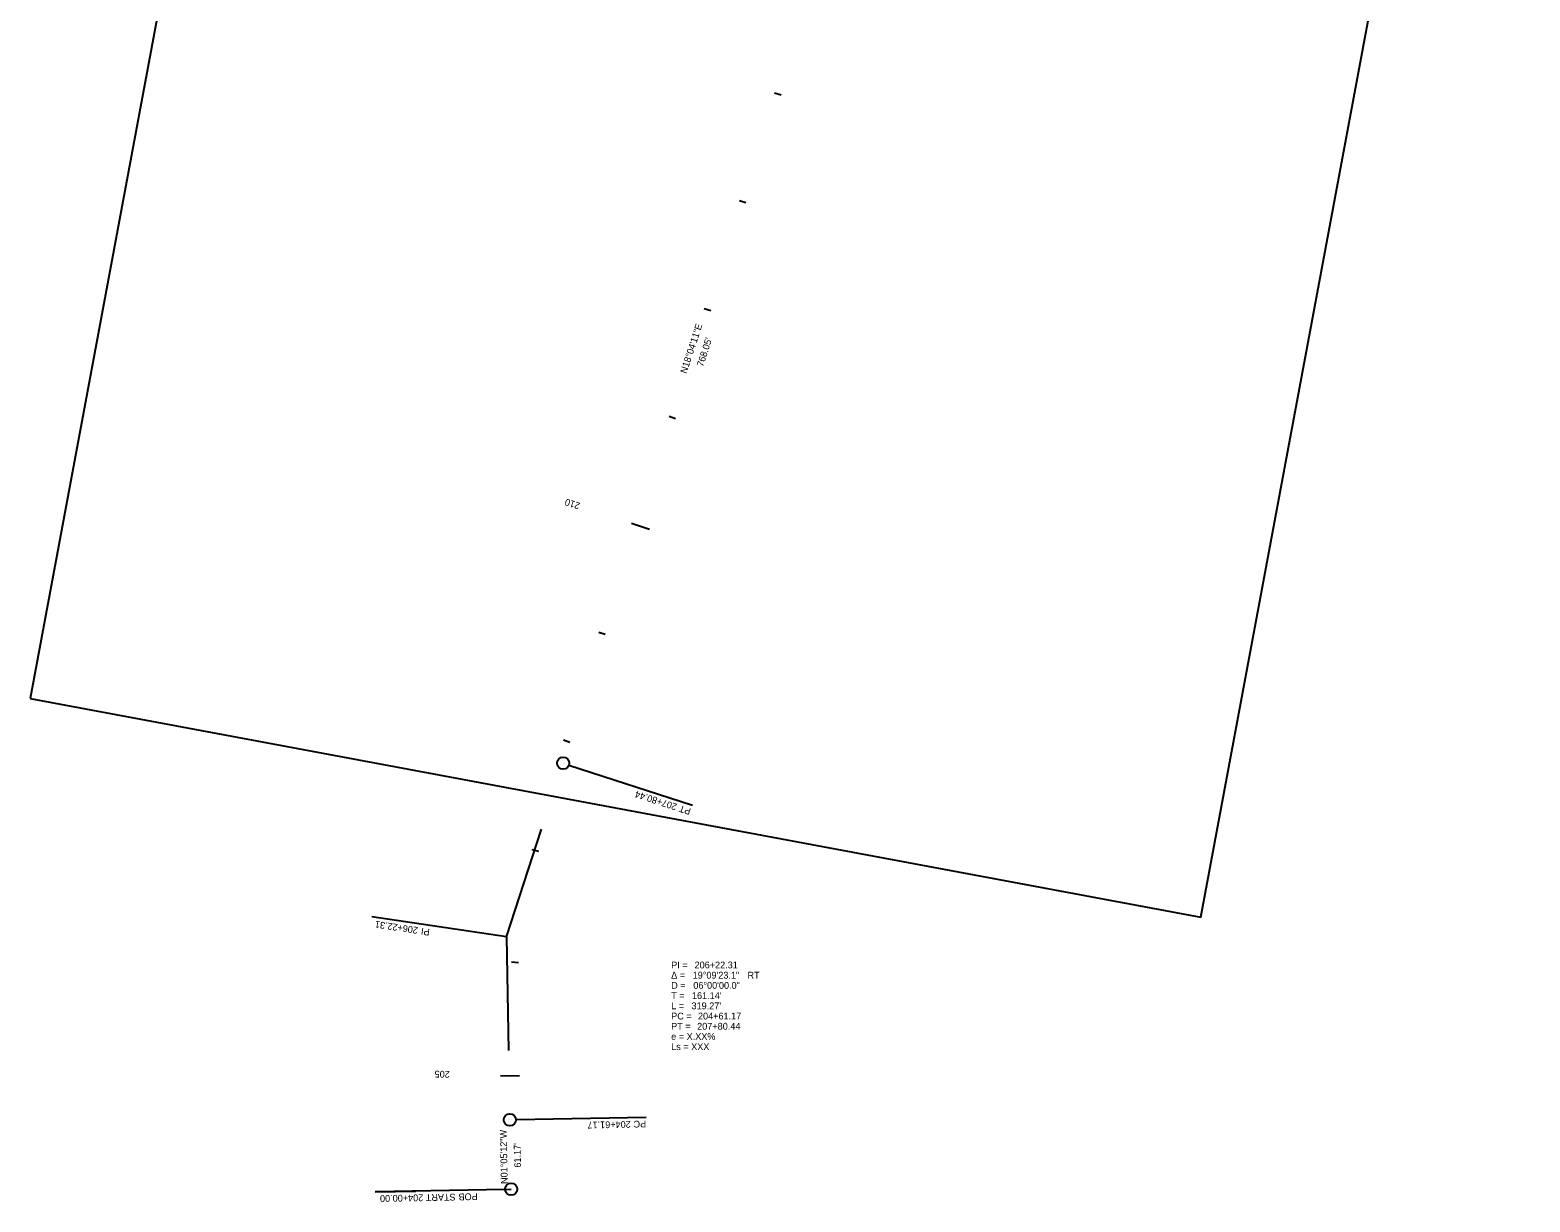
# Model space of a CAD drawing. Extents: x 1802363 to 1804577, y 570221 to 575010.
# Drawn here: x 1802779 to 1804101, y 572742 to 573774 of the extents above; entities that cross this region are included whole.
import ezdxf

# ---------------------------------------------------------------- set-up
doc = ezdxf.new("R2010")
doc.units = 0
for name, color, linetype in [('S_CROSS_DRAIN', 7, 'Continuous'), ('S_FENCE', 7, 'Continuous'), ('S_SIGN', 7, 'Continuous')]:
    doc.layers.add(name, color=color, linetype=linetype)

msp = doc.modelspace()

# ---------------------------------------------------------------- linework, layer by layer
at = {"layer": 'S_CROSS_DRAIN'}
for p, q in [((1803435.4, 573719.1), (1803441.1, 573717.3)), ((1803404.4, 573624.1), (1803410.1, 573622.2)), ((1803373.4, 573529), (1803379.1, 573527.1)), ((1803342.4, 573433.9), (1803348.1, 573432.1)), ((1803309.1, 573339.6), (1803325, 573334.4)), ((1803280.3, 573243.8), (1803286, 573241.9)), ((1803249.3, 573148.7), (1803255, 573146.9)), ((1803249, 573128.3), (1803249, 573128.3)), ((1803254, 573126.6), (1803363, 573091.1)), ((1803363, 573091.1), (1803363, 573091.1)), ((1803199, 572975.1), (1803230, 573070.2)), ((1803221.4, 573052.2), (1803227.3, 573050.8)), ((1803199, 572975.1), (1803080.3, 572992.8)), ((1803080.3, 572992.8), (1803080.3, 572992.8)), ((1803199, 572975.1), (1803200.9, 572875.1)), ((1803203.5, 572953.2), (1803209.5, 572952.5)), ((1803193.7, 572853), (1803210.5, 572852.6)), ((1803202, 572814), (1803202, 572814)), ((1803207.4, 572814.1), (1803322, 572816.3)), ((1803322, 572816.3), (1803322, 572816.3)), ((1803197.9, 572752.7), (1803083.2, 572750.5)), ((1803083.2, 572750.5), (1803119.2, 572751.2)), ((1803197.2, 572752.7), (1803203.2, 572752.8)), ((1803203.2, 572752.8), (1803203.2, 572752.8))]:
    msp.add_line(p, q, dxfattribs=at)
for centre in [(1803249, 573128.3), (1803202, 572814), (1803203.2, 572752.8)]:
    msp.add_circle(centre, 5.34, dxfattribs=at)
at = {"layer": 'S_SIGN'}
msp.add_lwpolyline([(1802779, 573185.2), (1803811.2, 572992.6), (1804101.3, 574547.6), (1803069.1, 574740.2)], close=True, dxfattribs=at)

# ---------------------------------------------------------------- texts
at = {"layer": 'S_CROSS_DRAIN'}
for s, rotation, p in [('N18°04\'11"E', 71.9303, (1803357.7, 573471.1)), ('210', 161.9303, (1803264.4, 573357.4)), ('207+80.44', 161.9303, (1803349.8, 573092.2)), ('PT', 161.9303, (1803362.1, 573088.2)), ('206+22.31', 171.5085, (1803121.3, 572983.7)), ('PI ', 171.5085, (1803131.7, 572982.1)), ('205', 178.757, (1803149.1, 572857)), ('204+61.17', 181.0867, (1803308.5, 572813)), ('PC', 181.0867, (1803322.1, 572813.3)), ('N01°05\'12"W', 91.0867, (1803200.1, 572757.5)), ('204+00.00', 181.0867, (1803125.6, 572748.3)), ('START', 181.0867, (1803154.1, 572748.9)), ('POB ', 181.0867, (1803173.6, 572749.3))]:
    msp.add_text(s, height=6, rotation=rotation, dxfattribs=at).set_placement(p)
for s, p in [('Δ = ', (1803344.2, 572938.4)), ('PI = ', (1803344.2, 572947.4)), ('19°09\'23.1"', (1803363.1, 572938.4)), ('206+22.31', (1803364.8, 572947.4)), (' RT', (1803409.3, 572938.4)), ('D = ', (1803344.2, 572929.4)), ('06°00\'00.0"', (1803363.7, 572929.4)), ('T = ', (1803344.2, 572920.4)), ('L = ', (1803344.2, 572911.4)), ("319.27'", (1803362.1, 572911.4)), ("161.14'", (1803362.5, 572920.4)), ('PC = ', (1803344.2, 572902.4)), ('204+61.17', (1803367.8, 572902.4)), ('e = X.XX%', (1803344.2, 572884.4)), ('PT = ', (1803344.2, 572893.4)), ('207+80.44', (1803367.1, 572893.4)), ('Ls = XXX', (1803344.2, 572875.4))]:
    msp.add_text(s, height=6, dxfattribs=at).set_placement(p)
at = {"layer": 'S_FENCE'}
for s, rotation, p in [("768.05'", 71.9303, (1803372.3, 573477.2)), ("61.17'", 91.0867, (1803211.8, 572771.9))]:
    msp.add_text(s, height=6, rotation=rotation, dxfattribs=at).set_placement(p)

doc.saveas('drawing.dxf')
